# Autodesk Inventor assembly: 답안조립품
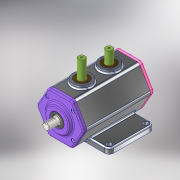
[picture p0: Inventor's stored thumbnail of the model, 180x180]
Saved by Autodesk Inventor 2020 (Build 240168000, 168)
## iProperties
Created: 2021-06
Part Number: 답안조립품
Document SubType Name: Assembly
Designer: MIRAE
Author: MIRAE
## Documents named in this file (11)
- C:\Users\MIRAE\Desktop\710606V1020\답안조립품.iam
- C:\Users\MIRAE\Desktop\710606V1020\본체.ipt
- C:\Users\MIRAE\Desktop\710606V1020\슬라이더.ipt
- C:\Users\MIRAE\Desktop\710606V1020\편심축.ipt
- C:\Users\MIRAE\Desktop\710606V1020\베어링 6203.ipt
- C:\Users\MIRAE\Desktop\710606V1020\베어링 6302.ipt
- C:\Users\MIRAE\Desktop\710606V1020\부시.ipt
- C:\Users\MIRAE\Desktop\710606V1020\뒷커버.ipt
- C:\Users\MIRAE\Desktop\710606V1020\볼트 M4.ipt
- C:\Users\MIRAE\Desktop\710606V1020\앞커버.ipt
- C:\Users\MIRAE\Desktop\710606V1020\오일실.ipt
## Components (10 placed, 3 different names)
1. 7-베어링 6203:1
2. 8-오일실:1
3. 9-M4-소켓머리:1
4. 9-M4-소켓머리:2
5. 9-M4-소켓머리:3
6. 9-M4-소켓머리:4
7. 9-M4-소켓머리:5
8. 9-M4-소켓머리:6
9. 9-M4-소켓머리:7
10. 9-M4-소켓머리:8
